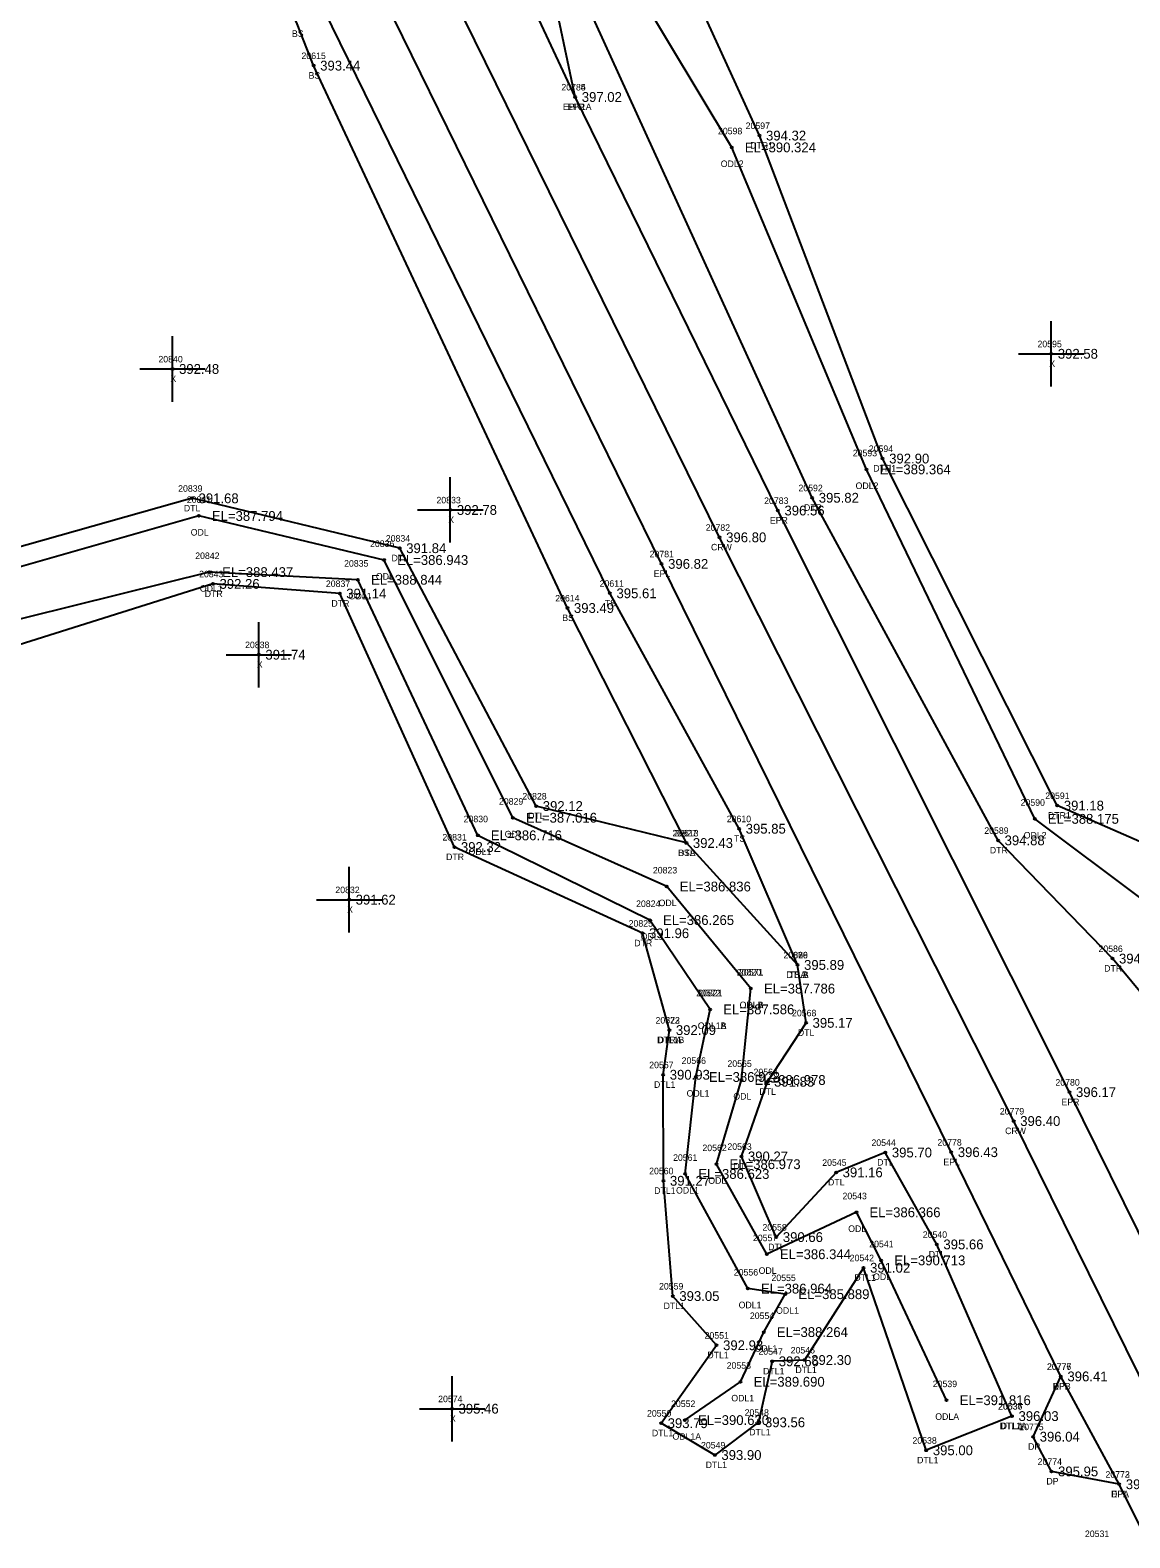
# Model space of a CAD drawing. Extents: x 2186623 to 2187804, y 1079975 to 1082766.
# Drawn here: x 2186882.3 to 2187050.6, y 1082125.2 to 1082355.8 of the extents above; entities that cross this region are included whole.
import ezdxf

# ---------------------------------------------------------------- set-up
doc = ezdxf.new("R2010")
doc.units = 0
for name, color, linetype in [('RD_DTM_BkLn1', 7, 'Continuous'), ('RD_DTM_BkLn2', 7, 'Continuous'), ('RD_DTM_BkLn_txCode', 7, 'Continuous'), ('RD_EX_Driveway', 7, 'Continuous'), ('RD_EX_Driveway_txCode', 7, 'Continuous'), ('RD_EX_H2O', 7, 'Continuous'), ('RD_EX_H2O_txCode', 7, 'Continuous'), ('RD_EX_Misc', 7, 'Continuous'), ('RD_EX_Misc_txCode', 7, 'Continuous'), ('RD_EX_Road', 7, 'Continuous'), ('RD_EX_Road_txCode', 7, 'Continuous'), ('RD_EX_TX_Driveway_ELEV', 7, 'Continuous'), ('RD_EX_TX_H2O_ELEV', 7, 'Continuous'), ('RD_EX_TX_Misc_ELEV', 7, 'Continuous'), ('RD_EX_TX_Road_ELEV', 7, 'Continuous'), ('RD_HC_Survey_ELEV', 7, 'Continuous'), ('RD_HC_Survey_txCode', 7, 'Continuous'), ('RD_SMD_Locator', 7, 'Continuous')]:
    doc.layers.add(name, color=color, linetype=linetype)

msp = doc.modelspace()

# ---------------------------------------------------------------- linework, layer by layer
at = {"layer": 'RD_DTM_BkLn1'}
msp.add_lwpolyline([(2187423.87, 1081398.18), (2187387.08, 1081472.03), (2187341.23, 1081563.21), (2187295.24, 1081657.28), (2187251.34, 1081744.68), (2187208.12, 1081834.1), (2187164.51, 1081922.08), (2187120.25, 1082011.57), (2187076.78, 1082099.89), (2187032.8, 1082188.99), (2186987.81, 1082278.27), (2186943.85, 1082367.59), (2186899.96, 1082456.58), (2186856.34, 1082544.86), (2186810.78, 1082636.89), (2186773.78, 1082711.06)], dxfattribs=at)
at = {"layer": 'RD_DTM_BkLn2'}
for points in [[(2186982.72, 1082231.52), (2186964.52, 1082267.46), (2186925.7, 1082350.42), (2186923.16, 1082356.81), (2186887.59, 1082435.8)], [(2186999.73, 1082212.87), (2186990.8, 1082233.7), (2186971.03, 1082269.71), (2186927.28, 1082359.01), (2186891.36, 1082437.21)]]:
    msp.add_lwpolyline(points, dxfattribs=at)
at = {"layer": 'RD_EX_Driveway'}
msp.add_lwpolyline([(2187048.95, 1082133.44), (2187038.59, 1082135.4), (2187035.78, 1082140.71), (2187040.02, 1082149.93)], dxfattribs=at)
at = {"layer": 'RD_EX_H2O'}
for points in [[(2187194.42, 1081921.93), (2187188.23, 1081917.94), (2187181.17, 1081931.31), (2187136.64, 1082019.21), (2187091.33, 1082107.81), (2187068.66, 1082159.56), (2187065.82, 1082182.56), (2187062.96, 1082190.59), (2187056.52, 1082203.47), (2187047.91, 1082213.84), (2187030.41, 1082231.92), (2187001.98, 1082284.32), (2186967.42, 1082359.95), (2186975.57, 1082384.17), (2187023.93, 1082440.63)], [(2187068.42, 1082209.99), (2187063.14, 1082216.42), (2187052.7, 1082222.74), (2187036.02, 1082235.21), (2187010.3, 1082288.66), (2186989.67, 1082337.91), (2186975, 1082362.36), (2186975.7, 1082367.63), (2186978.06, 1082371.76), (2187025.68, 1082438.74)], [(2187069.62, 1082212.47), (2187066.24, 1082217.84), (2187056.49, 1082229.79), (2187039.47, 1082237.24), (2187012.75, 1082290.32), (2186993.91, 1082339.72), (2186981.02, 1082367.99), (2187027.6, 1082436.93)], [(2187032.54, 1082143.86), (2187021.05, 1082170.12), (2187013.16, 1082184.18), (2187005.63, 1082181.14), (2186996.48, 1082171.24), (2186991.14, 1082183.58), (2186995.14, 1082195), (2187001.03, 1082204.01), (2186999.73, 1082212.87), (2186999.73, 1082212.87), (2186982.72, 1082231.52), (2186959.75, 1082237.17), (2186938.86, 1082276.61), (2186907.09, 1082284.24), (2186858.92, 1082270.65), (2186828.44, 1082235.81), (2186771.94, 1082213.63), (2186763.28, 1082212.29), (2186745.26, 1082252.66)], [(2187022.54, 1082146.29), (2187012.53, 1082167.68), (2187008.73, 1082175.03), (2186995.03, 1082168.62), (2186987.32, 1082182.39), (2186991.15, 1082195.27), (2186992.6, 1082209.25), (2186992.6, 1082209.25), (2186979.71, 1082224.86), (2186956.17, 1082235.38), (2186936.47, 1082274.8), (2186908.13, 1082281.54), (2186859.53, 1082267.71), (2186829.46, 1082233.57), (2186773.45, 1082209.61), (2186759.94, 1082210.67), (2186741.59, 1082251.07)], [(2186982.5, 1082143.25), (2186991.01, 1082149.11), (2186994.56, 1082156.71), (2186997.86, 1082162.51), (2186992.13, 1082163.36), (2186982.55, 1082180.9), (2186984.17, 1082195.73), (2186986.36, 1082206.07), (2186986.36, 1082206.07), (2186977.15, 1082219.73), (2186950.81, 1082232.69), (2186932.48, 1082271.78), (2186909.7, 1082272.95), (2186860.97, 1082260.86), (2186833.61, 1082224.48), (2186773.78, 1082204.8), (2186758.64, 1082205.49), (2186737.31, 1082245.01)], [(2186980.12, 1082202.9), (2186976.01, 1082217.72), (2186947.23, 1082230.9), (2186929.69, 1082269.67), (2186910.3, 1082271.15), (2186861.99, 1082255.97), (2186834.44, 1082222.66), (2186776.56, 1082198.63), (2186765, 1082197.27), (2186754.55, 1082205.01), (2186733.3, 1082242.83)], [(2187032.54, 1082143.86), (2187019.43, 1082138.63), (2187009.83, 1082166.55), (2187000.82, 1082152.44), (2186995.86, 1082152.24), (2186993.75, 1082142.91), (2186987.08, 1082137.91), (2186978.86, 1082142.78), (2186987.34, 1082154.7), (2186980.65, 1082162.22), (2186979.21, 1082179.85), (2186979.18, 1082196.07), (2186980.12, 1082202.9)]]:
    msp.add_lwpolyline(points, dxfattribs=at)
at = {"layer": 'RD_EX_Misc'}
for p, q in [((2187038.55, 1082301.34), (2187038.55, 1082311.34)), ((2186904.11, 1082299.02), (2186904.11, 1082309.02)), ((2187033.55, 1082306.34), (2187043.55, 1082306.34)), ((2186899.11, 1082304.02), (2186909.11, 1082304.02)), ((2186946.61, 1082277.46), (2186946.61, 1082287.46)), ((2186941.61, 1082282.46), (2186951.61, 1082282.46)), ((2186917.32, 1082255.32), (2186917.32, 1082265.32)), ((2186912.32, 1082260.32), (2186922.32, 1082260.32)), ((2186931.13, 1082217.85), (2186931.13, 1082227.85)), ((2186926.13, 1082222.85), (2186936.13, 1082222.85)), ((2186946.87, 1082139.99), (2186946.87, 1082149.99)), ((2186941.87, 1082144.99), (2186951.87, 1082144.99))]:
    msp.add_line(p, q, dxfattribs=at)
at = {"layer": 'RD_EX_Road'}
for points in [[(2187433.48, 1081402.93), (2187431.23, 1081405.14), (2187428.77, 1081409.96), (2187395.59, 1081476.3), (2187350.19, 1081567.64), (2187304.81, 1081661.14), (2187260.59, 1081749.11), (2187216.69, 1081837.7), (2187187.21, 1081897.62), (2187180.39, 1081911.5), (2187172.85, 1081926.68), (2187129.14, 1082015.5), (2187085.24, 1082104.53), (2187041.33, 1082193.41), (2186996.73, 1082282.37), (2186965.72, 1082345.62), (2186953.24, 1082372.4), (2186921.8, 1082435.38), (2186908.96, 1082460.32), (2186865.29, 1082548.82), (2186820.07, 1082641.92), (2186783.9, 1082716)], [(2187412.76, 1081392.41), (2187413.27, 1081397.3), (2187377.92, 1081468.69), (2187333.03, 1081559.63), (2187287.24, 1081651.83), (2187243.42, 1081739.85), (2187221.49, 1081785.01), (2187215.17, 1081798.71), (2187200.07, 1081829.29), (2187156, 1081917.87), (2187111.96, 1082007.49), (2187067.92, 1082095.45), (2187048.95, 1082133.44), (2187040.02, 1082149.93), (2187023.25, 1082184.23), (2186978.93, 1082274.21), (2186935.28, 1082363.16), (2186891.66, 1082452.64), (2186848.32, 1082541.12), (2186802.48, 1082632.77), (2186765.18, 1082707.62)], [(2186965.72, 1082345.62), (2186963, 1082358.46), (2186965.23, 1082372.1), (2186969.67, 1082384.97), (2186980.44, 1082404.5), (2186998.29, 1082422.58), (2187016.75, 1082444.57)]]:
    msp.add_lwpolyline(points, dxfattribs=at)
at = {"layer": 'RD_SMD_Locator'}
for centre in [(2186925.7, 1082350.42), (2186965.72, 1082345.62), (2186965.72, 1082345.62), (2186993.91, 1082339.72), (2186989.67, 1082337.91), (2187038.55, 1082306.34), (2186904.11, 1082304.02), (2187010.3, 1082288.66), (2187012.75, 1082290.32), (2186907.09, 1082284.24), (2187001.98, 1082284.32), (2186908.13, 1082281.54), (2186946.61, 1082282.46), (2186996.73, 1082282.37), (2186938.86, 1082276.61), (2186987.81, 1082278.27), (2186936.47, 1082274.8), (2186978.93, 1082274.21), (2186909.7, 1082272.95), (2186910.3, 1082271.15), (2186929.69, 1082269.67), (2186932.48, 1082271.78), (2186971.03, 1082269.71), (2186964.52, 1082267.46), (2186917.32, 1082260.32), (2186956.17, 1082235.38), (2186959.75, 1082237.17), (2187036.02, 1082235.21), (2187039.47, 1082237.24), (2186950.81, 1082232.69), (2186990.8, 1082233.7), (2186947.23, 1082230.9), (2186982.72, 1082231.52), (2186982.72, 1082231.52), (2187030.41, 1082231.92), (2186979.71, 1082224.86), (2186931.13, 1082222.85), (2186977.15, 1082219.73), (2186976.01, 1082217.72), (2186999.73, 1082212.87), (2186999.73, 1082212.87), (2186999.73, 1082212.87), (2187047.91, 1082213.84), (2186992.6, 1082209.25), (2186992.6, 1082209.25), (2186986.36, 1082206.07), (2186986.36, 1082206.07), (2186980.12, 1082202.9), (2186980.12, 1082202.9), (2187001.03, 1082204.01), (2186979.18, 1082196.07), (2186984.17, 1082195.73), (2186991.15, 1082195.27), (2186995.14, 1082195), (2187041.33, 1082193.41), (2187032.8, 1082188.99), (2186987.32, 1082182.39), (2186991.14, 1082183.58), (2187013.16, 1082184.18), (2187023.25, 1082184.23), (2186979.21, 1082179.85), (2186982.55, 1082180.9), (2187005.63, 1082181.14), (2187008.73, 1082175.03), (2186996.48, 1082171.24), (2186995.03, 1082168.62), (2187021.05, 1082170.12), (2187009.83, 1082166.55), (2187012.53, 1082167.68), (2186980.65, 1082162.22), (2186992.13, 1082163.36), (2186997.86, 1082162.51), (2186994.56, 1082156.71), (2186987.34, 1082154.7), (2186995.86, 1082152.24), (2187000.82, 1082152.44), (2187040.02, 1082149.93), (2187040.02, 1082149.93), (2186991.01, 1082149.11), (2187022.54, 1082146.29), (2186946.87, 1082144.99), (2186978.86, 1082142.78), (2186982.5, 1082143.25), (2186993.75, 1082142.91), (2187032.54, 1082143.86), (2187032.54, 1082143.86), (2187035.78, 1082140.71), (2187019.43, 1082138.63), (2186987.08, 1082137.91), (2187038.59, 1082135.4), (2187048.95, 1082133.44), (2187048.95, 1082133.44)]:
    msp.add_circle(centre, 0.15, dxfattribs=at)

# ---------------------------------------------------------------- texts
at = {"layer": 'RD_DTM_BkLn_txCode'}
for s, p in [('BS', (2186922.38, 1082354.81)), ('20615', (2186923.84, 1082351.42)), ('BS', (2186924.92, 1082348.42)), ('20611', (2186969.45, 1082270.71)), ('20614', (2186962.66, 1082268.46)), ('TS', (2186970.23, 1082267.71)), ('BS', (2186963.74, 1082265.46)), ('20610', (2186988.9, 1082234.7)), ('20613', (2186980.86, 1082232.52)), ('BSA', (2186981.45, 1082229.52)), ('TS', (2186990.01, 1082231.7)), ('20570', (2186997.57, 1082213.87)), ('TSA', (2186998.45, 1082210.87))]:
    msp.add_text(s, height=1, dxfattribs=at).set_placement(p)
at = {"layer": 'RD_EX_Driveway_txCode'}
for s, p in [('20776', (2187037.88, 1082150.93)), ('DPB', (2187038.77, 1082147.93)), ('20775', (2187033.66, 1082141.71)), ('DP', (2187035, 1082138.71)), ('20774', (2187036.47, 1082136.4)), ('DP', (2187037.81, 1082133.4)), ('20773', (2187046.84, 1082134.44)), ('DPA', (2187047.69, 1082131.44))]:
    msp.add_text(s, height=1, dxfattribs=at).set_placement(p)
at = {"layer": 'RD_EX_H2O_txCode'}
for s, p in [('20597', (2186991.79, 1082340.72)), ('20598', (2186987.56, 1082339.91)), ('DTR1', (2186992.48, 1082337.72)), ('ODL2', (2186987.98, 1082334.91)), ('20593', (2187008.18, 1082290.66)), ('20594', (2187010.63, 1082291.32)), ('DTR1', (2187011.32, 1082288.32)), ('20839', (2186904.97, 1082285.24)), ('20592', (2186999.87, 1082285.32)), ('ODL2', (2187008.61, 1082285.66)), ('20841', (2186906.3, 1082283.54)), ('DTL', (2186905.84, 1082282.24)), ('DTR', (2187000.72, 1082282.32)), ('ODL', (2186906.89, 1082278.54)), ('20836', (2186934.33, 1082276.8)), ('20834', (2186936.74, 1082277.61)), ('20842', (2186907.58, 1082274.95)), ('20835', (2186930.36, 1082273.78)), ('DTL', (2186937.62, 1082274.61)), ('20843', (2186908.18, 1082272.15)), ('ODL', (2186935.22, 1082271.8)), ('ODL1', (2186908.29, 1082269.95)), ('DTR', (2186909.03, 1082269.15)), ('20837', (2186927.57, 1082270.67)), ('ODL1', (2186931.07, 1082268.78)), ('DTR', (2186928.42, 1082267.67)), ('20829', (2186954.05, 1082237.38)), ('20828', (2186957.63, 1082238.17)), ('20590', (2187033.86, 1082237.21)), ('20591', (2187037.63, 1082238.24)), ('20830', (2186948.65, 1082234.69)), ('DTL', (2186958.51, 1082235.17)), ('DTR1', (2187038.04, 1082235.24)), ('20831', (2186945.4, 1082231.9)), ('ODL', (2186954.93, 1082232.38)), ('20827', (2186980.6, 1082232.52)), ('20589', (2187028.3, 1082232.92)), ('ODL2', (2187034.33, 1082232.21)), ('ODL1', (2186949.4, 1082229.69)), ('DTR', (2187029.15, 1082229.92)), ('DTR', (2186945.96, 1082228.9)), ('DTL', (2186981.48, 1082229.52)), ('20823', (2186977.6, 1082226.86)), ('20824', (2186975.03, 1082221.73)), ('ODL', (2186978.47, 1082221.86)), ('20825', (2186973.89, 1082218.72)), ('DTR', (2186974.75, 1082215.72)), ('ODL1', (2186975.74, 1082216.73)), ('20569', (2186997.59, 1082213.87)), ('20826', (2186997.59, 1082213.87)), ('20586', (2187045.77, 1082214.84)), ('20820', (2186990.44, 1082211.25)), ('20571', (2186990.77, 1082211.25)), ('DTR', (2187046.64, 1082211.84)), ('DTLA', (2186998, 1082210.87)), ('DTLB', (2186998.01, 1082210.87)), ('20572', (2186984.24, 1082208.07)), ('20821', (2186984.53, 1082208.07)), ('ODLA', (2186990.87, 1082206.25)), ('ODLB', (2186990.88, 1082206.25)), ('20568', (2186998.89, 1082205.01)), ('20573', (2186978, 1082203.9)), ('20822', (2186978, 1082203.9)), ('ODL1A', (2186984.46, 1082203.07)), ('ODL1B', (2186984.48, 1082203.07)), ('DTL', (2186999.78, 1082202.01)), ('DTL1B', (2186978.24, 1082200.9)), ('DTRA', (2186978.36, 1082200.9)), ('20566', (2186982, 1082197.73)), ('20565', (2186989.01, 1082197.27)), ('20567', (2186977.04, 1082197.07)), ('20564', (2186993, 1082196)), ('DTL1', (2186977.77, 1082194.07)), ('ODL1', (2186982.76, 1082192.73)), ('DTL', (2186993.9, 1082193)), ('ODL', (2186989.91, 1082192.27)), ('20562', (2186985.18, 1082184.39)), ('20563', (2186989, 1082184.58)), ('20544', (2187011.04, 1082185.18)), ('20561', (2186980.69, 1082182.9)), ('DTL', (2186989.9, 1082181.58)), ('20545', (2187003.51, 1082182.14)), ('DTL', (2187011.91, 1082182.18)), ('20560', (2186977.03, 1082180.85)), ('ODL', (2186986.08, 1082179.39)), ('DTL', (2187004.39, 1082179.14)), ('DTL1', (2186977.8, 1082177.85)), ('ODL1', (2186981.14, 1082177.9)), ('20543', (2187006.61, 1082177.03)), ('20558', (2186994.36, 1082172.24)), ('ODL', (2187007.48, 1082172.03)), ('20557', (2186992.91, 1082170.62)), ('20541', (2187010.7, 1082169.68)), ('20540', (2187018.89, 1082171.12)), ('DTL', (2186995.23, 1082169.24)), ('20542', (2187007.71, 1082167.55)), ('DTL', (2187019.8, 1082168.12)), ('20556', (2186989.98, 1082165.36)), ('ODL', (2186993.78, 1082165.62)), ('20559', (2186978.54, 1082163.22)), ('20555', (2186995.74, 1082164.51)), ('DTL1', (2187008.42, 1082164.55)), ('ODL', (2187011.29, 1082164.68)), ('ODL1', (2186990.72, 1082160.36)), ('DTL1', (2186979.24, 1082160.22)), ('20554', (2186992.44, 1082158.71)), ('ODL1', (2186996.45, 1082159.51)), ('20551', (2186985.51, 1082155.7)), ('ODL1', (2186993.15, 1082153.71)), ('20546', (2186998.68, 1082153.44)), ('DTL1', (2186985.93, 1082152.7)), ('20553', (2186988.89, 1082151.11)), ('20547', (2186993.75, 1082153.24)), ('DTL1', (2186994.45, 1082150.24)), ('DTL1', (2186999.41, 1082150.44)), ('20539', (2187020.42, 1082148.29)), ('20552', (2186980.38, 1082145.25)), ('ODL1', (2186989.6, 1082146.11)), ('20536', (2187030.4, 1082144.86)), ('20537', (2187030.43, 1082144.86)), ('20550', (2186976.7, 1082143.78)), ('20548', (2186991.63, 1082143.91)), ('ODLA', (2187020.8, 1082143.29)), ('DTL1', (2186977.45, 1082140.78)), ('ODL1A', (2186980.6, 1082140.25)), ('DTL1', (2186992.34, 1082140.91)), ('20538', (2187017.31, 1082139.63)), ('DTL1A', (2187030.65, 1082141.86)), ('DTLA', (2187030.81, 1082141.86)), ('20549', (2186984.96, 1082138.91)), ('DTL1', (2186985.67, 1082135.91)), ('DTL1', (2187018.02, 1082136.63)), ('20531', (2187043.7, 1082125.36))]:
    msp.add_text(s, height=1, dxfattribs=at).set_placement(p)
at = {"layer": 'RD_EX_Misc_txCode'}
for s, p in [('20595', (2187036.44, 1082307.34)), ('20840', (2186901.95, 1082305.02)), ('X', (2187038.24, 1082304.34)), ('X', (2186903.79, 1082302.02)), ('20833', (2186944.49, 1082283.46)), ('X', (2186946.29, 1082280.46)), ('20838', (2186915.21, 1082261.32)), ('X', (2186917.01, 1082258.32)), ('20832', (2186929.02, 1082223.85)), ('X', (2186930.82, 1082220.85)), ('20574', (2186944.75, 1082145.99)), ('X', (2186946.56, 1082142.99))]:
    msp.add_text(s, height=1, dxfattribs=at).set_placement(p)
at = {"layer": 'RD_EX_Road_txCode'}
for s, p in [('20784', (2186963.6, 1082346.62)), ('20785', (2186963.6, 1082346.62)), ('EPR1A', (2186963.83, 1082343.62)), ('EPR', (2186964.49, 1082343.62)), ('20783', (2186994.62, 1082283.37)), ('EPR', (2186995.5, 1082280.37)), ('20781', (2186977.1, 1082275.21)), ('EPL', (2186977.73, 1082272.21)), ('20780', (2187039.18, 1082194.41)), ('EPR', (2187040.11, 1082191.41)), ('20778', (2187021.13, 1082185.23)), ('EPL', (2187022.05, 1082182.23)), ('20777', (2187037.91, 1082150.93)), ('EPL', (2187038.82, 1082147.93)), ('20772', (2187046.84, 1082134.44)), ('EPL', (2187047.75, 1082131.44))]:
    msp.add_text(s, height=1, dxfattribs=at).set_placement(p)
at = {"layer": 'RD_EX_TX_Driveway_ELEV'}
for s, p in [('396.41', (2187041.02, 1082149.18)), ('396.04', (2187036.78, 1082139.96)), ('395.95', (2187039.59, 1082134.65)), ('396.25', (2187049.95, 1082132.69))]:
    msp.add_text(s, height=1.5, dxfattribs=at).set_placement(p)
at = {"layer": 'RD_EX_TX_H2O_ELEV'}
for s, p in [('394.32', (2186994.91, 1082338.97)), ('EL=390.324', (2186991.67, 1082337.16)), ('392.90', (2187013.75, 1082289.57)), ('EL=389.364', (2187012.3, 1082287.91)), ('391.68', (2186908.09, 1082283.49)), ('395.82', (2187002.98, 1082283.57)), ('EL=387.794', (2186910.13, 1082280.79)), ('391.84', (2186939.86, 1082275.86)), ('EL=386.943', (2186938.47, 1082274.05)), ('EL=388.437', (2186911.7, 1082272.2)), ('EL=388.844', (2186934.48, 1082271.03)), ('392.26', (2186911.3, 1082270.4)), ('391.14', (2186930.69, 1082268.92)), ('392.12', (2186960.75, 1082236.42)), ('391.18', (2187040.47, 1082236.49)), ('EL=387.016', (2186958.17, 1082234.63)), ('EL=388.175', (2187038.02, 1082234.46)), ('EL=386.716', (2186952.81, 1082231.94)), ('392.32', (2186948.23, 1082230.15)), ('392.43', (2186983.72, 1082230.77)), ('394.88', (2187031.41, 1082231.17)), ('EL=386.836', (2186981.71, 1082224.11)), ('EL=386.265', (2186979.15, 1082218.98)), ('391.96', (2186977.01, 1082216.97)), ('394.99', (2187048.91, 1082213.09)), ('395.89', (2187000.73, 1082212.12)), ('395.89', (2187000.73, 1082212.12)), ('EL=387.786', (2186994.6, 1082208.5)), ('EL=387.786', (2186994.6, 1082208.5)), ('EL=387.586', (2186988.36, 1082205.32)), ('EL=387.586', (2186988.36, 1082205.32)), ('392.09', (2186981.12, 1082202.15)), ('392.09', (2186981.12, 1082202.15)), ('395.17', (2187002.03, 1082203.26)), ('390.93', (2186980.18, 1082195.32)), ('EL=386.928', (2186986.17, 1082194.98)), ('EL=386.978', (2186993.15, 1082194.52)), ('391.83', (2186996.14, 1082194.25)), ('395.70', (2187014.16, 1082183.43)), ('EL=386.973', (2186989.32, 1082181.64)), ('390.27', (2186992.14, 1082182.83)), ('391.27', (2186980.21, 1082179.1)), ('EL=386.623', (2186984.55, 1082180.15)), ('391.16', (2187006.63, 1082180.39)), ('EL=386.366', (2187010.73, 1082174.28)), ('390.66', (2186997.48, 1082170.49)), ('395.66', (2187022.05, 1082169.37)), ('EL=386.344', (2186997.03, 1082167.87)), ('EL=390.713', (2187014.53, 1082166.93)), ('391.02', (2187010.83, 1082165.8)), ('EL=386.964', (2186994.13, 1082162.61)), ('393.05', (2186981.65, 1082161.47)), ('EL=385.889', (2186999.86, 1082161.76)), ('EL=388.264', (2186996.56, 1082155.96)), ('392.93', (2186988.34, 1082153.95)), ('392.66', (2186996.86, 1082151.49)), ('392.30', (2187001.82, 1082151.69)), ('EL=389.690', (2186993.01, 1082148.36)), ('EL=391.816', (2187024.54, 1082145.54)), ('393.79', (2186979.86, 1082142.03)), ('EL=390.630', (2186984.5, 1082142.5)), ('393.56', (2186994.75, 1082142.16)), ('396.03', (2187033.54, 1082143.11)), ('396.03', (2187033.54, 1082143.11)), ('393.90', (2186988.08, 1082137.16)), ('395.00', (2187020.43, 1082137.88))]:
    msp.add_text(s, height=1.5, dxfattribs=at).set_placement(p)
at = {"layer": 'RD_EX_TX_Misc_ELEV'}
for s, p in [('393.44', (2186926.7, 1082349.67)), ('392.58', (2187039.55, 1082305.59)), ('392.48', (2186905.11, 1082303.27)), ('392.78', (2186947.61, 1082281.71)), ('395.61', (2186972.03, 1082268.96)), ('393.49', (2186965.52, 1082266.71)), ('391.74', (2186918.32, 1082259.57)), ('395.85', (2186991.8, 1082232.95)), ('392.43', (2186983.72, 1082230.77)), ('391.62', (2186932.13, 1082222.1)), ('395.89', (2187000.73, 1082212.12)), ('395.46', (2186947.87, 1082144.24))]:
    msp.add_text(s, height=1.5, dxfattribs=at).set_placement(p)
at = {"layer": 'RD_EX_TX_Road_ELEV'}
for s, p in [('397.02', (2186966.72, 1082344.87)), ('397.02', (2186966.72, 1082344.87)), ('396.56', (2186997.73, 1082281.62)), ('396.82', (2186979.93, 1082273.46)), ('396.17', (2187042.33, 1082192.66)), ('396.43', (2187024.25, 1082183.48)), ('396.41', (2187041.02, 1082149.18)), ('396.25', (2187049.95, 1082132.69))]:
    msp.add_text(s, height=1.5, dxfattribs=at).set_placement(p)
at = {"layer": 'RD_HC_Survey_ELEV'}
for s, p in [('396.80', (2186988.81, 1082277.52)), ('396.40', (2187033.8, 1082188.24))]:
    msp.add_text(s, height=1.5, dxfattribs=at).set_placement(p)
at = {"layer": 'RD_HC_Survey_txCode'}
for s, p in [('20782', (2186985.69, 1082279.27)), ('CRW', (2186986.49, 1082276.27)), ('20779', (2187030.68, 1082189.99)), ('CRW', (2187031.49, 1082186.99))]:
    msp.add_text(s, height=1, dxfattribs=at).set_placement(p)

doc.saveas('drawing.dxf')
